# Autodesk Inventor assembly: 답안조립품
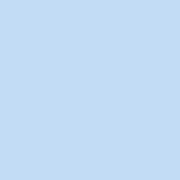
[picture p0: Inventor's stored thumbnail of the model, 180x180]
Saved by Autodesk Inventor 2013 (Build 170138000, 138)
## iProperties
Created: 2017-01
Part Number: 답안조립품
Document SubType Name: Assembly
Designer: dgall
Author: dgall
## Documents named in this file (1)
- C:\Users\dgall\Desktop\470107V1006\답안조립품.iam
